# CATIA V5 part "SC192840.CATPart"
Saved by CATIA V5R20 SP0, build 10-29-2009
Part number: SC192840
Revision: ANY
Definition: UNKNOWN
Nomenclature: SC192840
Source: Unknown
Bounding box of the stored display mesh (mm): x -8.473 to 10.44, y 0 to 28, z -40 to 0
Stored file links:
  C:\Users\Utente\Desktop\IO LAVORO\3D X SITO CF\CUMSA\3D files CG\CG 754049\SC192840.CATPart
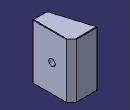
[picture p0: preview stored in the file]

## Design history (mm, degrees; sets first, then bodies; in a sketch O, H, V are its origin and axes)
Body1 "Chaflán2" (main body)
  Solid1: solid without history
